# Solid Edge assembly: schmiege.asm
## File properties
Author: administrator
Template: normal.asm
Last saved by: ra-11
Revision: 15
Application: Solid Edge
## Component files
hrungsplatte.par
Lineal.par
Scheibe.par
Anschlagwinkel.par
gelschraube.par
Zylinderstift.par
Senkkopfschraube M4.par
